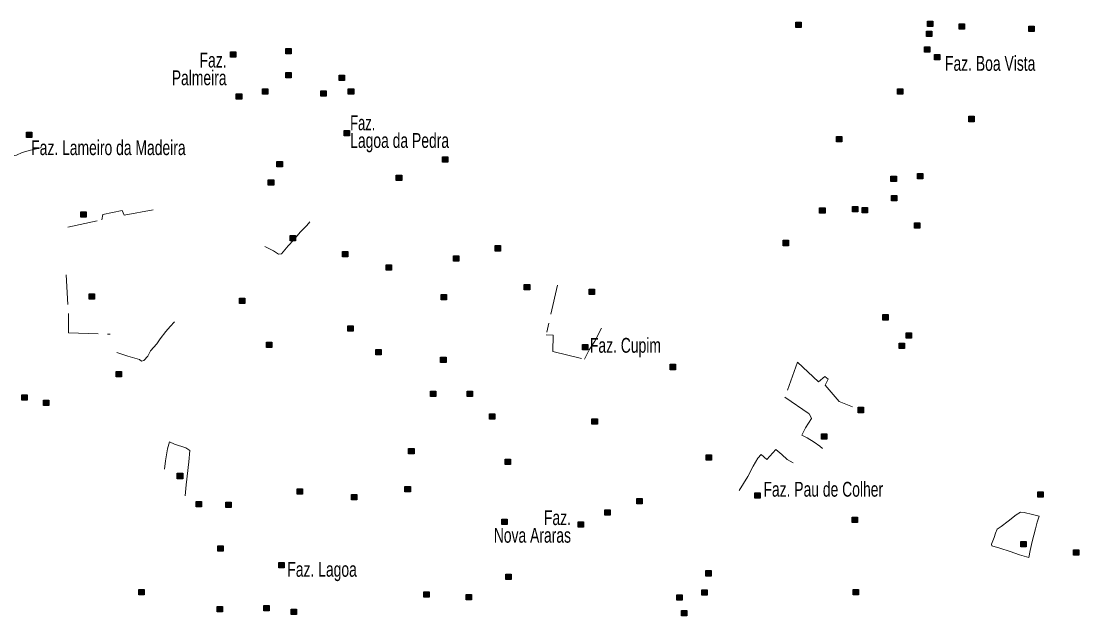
# Model space of a CAD drawing. Extents: x 445.4 to 500, y 8728.7 to 8784.
# Drawn here: x 488.04 to 499.45, y 8757.93 to 8764.34 of the extents above; entities that cross this region are included whole.
import ezdxf
from ezdxf.enums import TextEntityAlignment as Align

# ---------------------------------------------------------------- set-up
doc = ezdxf.new("R2010")
doc.units = 0
doc.header["$LTSCALE"] = 0.064
doc.linetypes.add('DOT_DASHED', pattern=[7.7, 5, -1.2, 0.3, -1.2])
doc.layers.add('2', color=7, linetype='Continuous', lineweight=25)
doc.layers.add('22', color=7, linetype='DOT_DASHED', lineweight=13)
doc.layers.add('61', color=7, linetype='Continuous')

msp = doc.modelspace()

# ---------------------------------------------------------------- hatches: boundary and pattern name
at = {"layer": '2'}
for points in [[(496.3962, 8764.3261), (496.4542, 8764.3261), (496.4542, 8764.2681), (496.3962, 8764.2681)], [(497.8159, 8764.336), (497.8739, 8764.336), (497.8739, 8764.278), (497.8159, 8764.278)], [(498.156, 8764.3064), (498.214, 8764.3064), (498.214, 8764.2484), (498.156, 8764.2484)], [(497.806, 8764.2275), (497.864, 8764.2275), (497.864, 8764.1695), (497.806, 8764.1695)], [(498.9079, 8764.2812), (498.9659, 8764.2812), (498.9659, 8764.2232), (498.9079, 8764.2232)], [(497.7814, 8764.0598), (497.8394, 8764.0598), (497.8394, 8764.0018), (497.7814, 8764.0018)], [(490.2987, 8764.0055), (490.3567, 8764.0055), (490.3567, 8763.9475), (490.2987, 8763.9475)], [(490.8959, 8764.0407), (490.9539, 8764.0407), (490.9539, 8763.9827), (490.8959, 8763.9827)], [(497.8898, 8763.976), (497.9478, 8763.976), (497.9478, 8763.918), (497.8898, 8763.918)], [(490.8952, 8763.7836), (490.9532, 8763.7836), (490.9532, 8763.7256), (490.8952, 8763.7256)], [(491.4719, 8763.754), (491.5299, 8763.754), (491.5299, 8763.696), (491.4719, 8763.696)], [(490.6438, 8763.606), (490.7018, 8763.606), (490.7018, 8763.548), (490.6438, 8763.548)], [(491.5705, 8763.606), (491.6285, 8763.606), (491.6285, 8763.548), (491.5705, 8763.548)], [(497.4905, 8763.6061), (497.5485, 8763.6061), (497.5485, 8763.5481), (497.4905, 8763.5481)], [(490.3628, 8763.5518), (490.4208, 8763.5518), (490.4208, 8763.4938), (490.3628, 8763.4938)], [(491.2747, 8763.5863), (491.3327, 8763.5863), (491.3327, 8763.5283), (491.2747, 8763.5283)], [(498.2595, 8763.3102), (498.3175, 8763.3102), (498.3175, 8763.2522), (498.2595, 8763.2522)], [(491.5261, 8763.1573), (491.5841, 8763.1573), (491.5841, 8763.0993), (491.5261, 8763.0993)], [(488.1002, 8763.1397), (488.1582, 8763.1397), (488.1582, 8763.0817), (488.1002, 8763.0817)], [(496.8349, 8763.0932), (496.8929, 8763.0932), (496.8929, 8763.0352), (496.8349, 8763.0352)], [(490.8015, 8762.8239), (490.8595, 8762.8239), (490.8595, 8762.7659), (490.8015, 8762.7659)], [(492.5859, 8762.8732), (492.6439, 8762.8732), (492.6439, 8762.8152), (492.5859, 8762.8152)], [(497.7074, 8762.6937), (497.7654, 8762.6937), (497.7654, 8762.6357), (497.7074, 8762.6357)], [(490.7078, 8762.6266), (490.7658, 8762.6266), (490.7658, 8762.5686), (490.7078, 8762.5686)], [(492.088, 8762.676), (492.146, 8762.676), (492.146, 8762.618), (492.088, 8762.618)], [(497.4215, 8762.6641), (497.4795, 8762.6641), (497.4795, 8762.6061), (497.4215, 8762.6061)], [(497.4284, 8762.4559), (497.4864, 8762.4559), (497.4864, 8762.3979), (497.4284, 8762.3979)], [(488.6868, 8762.2816), (488.7448, 8762.2816), (488.7448, 8762.2236), (488.6868, 8762.2236)], [(496.6526, 8762.3238), (496.7106, 8762.3238), (496.7106, 8762.2658), (496.6526, 8762.2658)], [(497.0075, 8762.3386), (497.0655, 8762.3386), (497.0655, 8762.2806), (497.0075, 8762.2806)], [(497.111, 8762.3288), (497.169, 8762.3288), (497.169, 8762.2708), (497.111, 8762.2708)], [(497.6745, 8762.1617), (497.7325, 8762.1617), (497.7325, 8762.1037), (497.6745, 8762.1037)], [(490.9444, 8762.025), (491.0024, 8762.025), (491.0024, 8761.967), (490.9444, 8761.967)], [(493.1527, 8761.9165), (493.2107, 8761.9165), (493.2107, 8761.8585), (493.1527, 8761.8585)], [(496.2582, 8761.9737), (496.3162, 8761.9737), (496.3162, 8761.9157), (496.2582, 8761.9157)], [(491.5064, 8761.8524), (491.5644, 8761.8524), (491.5644, 8761.7944), (491.5064, 8761.7944)], [(492.7042, 8761.808), (492.7622, 8761.808), (492.7622, 8761.75), (492.7042, 8761.75)], [(491.9796, 8761.7093), (492.0376, 8761.7093), (492.0376, 8761.6513), (491.9796, 8761.6513)], [(493.4682, 8761.4973), (493.5262, 8761.4973), (493.5262, 8761.4393), (493.4682, 8761.4393)], [(494.1682, 8761.448), (494.2262, 8761.448), (494.2262, 8761.39), (494.1682, 8761.39)], [(488.7756, 8761.3969), (488.8336, 8761.3969), (488.8336, 8761.3389), (488.7756, 8761.3389)], [(490.3973, 8761.3493), (490.4553, 8761.3493), (490.4553, 8761.2913), (490.3973, 8761.2913)], [(492.5711, 8761.3888), (492.6291, 8761.3888), (492.6291, 8761.3308), (492.5711, 8761.3308)], [(497.3328, 8761.1725), (497.3908, 8761.1725), (497.3908, 8761.1145), (497.3328, 8761.1145)], [(491.5655, 8761.0534), (491.6235, 8761.0534), (491.6235, 8760.9954), (491.5655, 8760.9954)], [(497.5842, 8760.9775), (497.6422, 8760.9775), (497.6422, 8760.9195), (497.5842, 8760.9195)], [(490.6881, 8760.8759), (490.7461, 8760.8759), (490.7461, 8760.8179), (490.6881, 8760.8179)], [(497.5103, 8760.8641), (497.5683, 8760.8641), (497.5683, 8760.8061), (497.5103, 8760.8061)], [(491.8662, 8760.797), (491.9242, 8760.797), (491.9242, 8760.739), (491.8662, 8760.739)], [(494.0942, 8760.8512), (494.1522, 8760.8512), (494.1522, 8760.7932), (494.0942, 8760.7932)], [(492.5662, 8760.7131), (492.6242, 8760.7131), (492.6242, 8760.6551), (492.5662, 8760.6551)], [(495.0407, 8760.6372), (495.0987, 8760.6372), (495.0987, 8760.5792), (495.0407, 8760.5792)], [(489.0664, 8760.5605), (489.1244, 8760.5605), (489.1244, 8760.5025), (489.0664, 8760.5025)], [(488.051, 8760.309), (488.109, 8760.309), (488.109, 8760.251), (488.051, 8760.251)], [(492.4577, 8760.3482), (492.5157, 8760.3482), (492.5157, 8760.2902), (492.4577, 8760.2902)], [(492.8521, 8760.3482), (492.9101, 8760.3482), (492.9101, 8760.2902), (492.8521, 8760.2902)], [(488.2826, 8760.2498), (488.3406, 8760.2498), (488.3406, 8760.1918), (488.2826, 8760.1918)], [(493.0936, 8760.1036), (493.1516, 8760.1036), (493.1516, 8760.0456), (493.0936, 8760.0456)], [(497.0666, 8760.1737), (497.1246, 8760.1737), (497.1246, 8760.1157), (497.0666, 8760.1157)], [(494.1977, 8760.0494), (494.2557, 8760.0494), (494.2557, 8759.9914), (494.1977, 8759.9914)], [(496.6723, 8759.8876), (496.7303, 8759.8876), (496.7303, 8759.8296), (496.6723, 8759.8296)], [(492.2211, 8759.7288), (492.2791, 8759.7288), (492.2791, 8759.6708), (492.2211, 8759.6708)], [(493.2612, 8759.6154), (493.3192, 8759.6154), (493.3192, 8759.5574), (493.2612, 8759.5574)], [(495.4301, 8759.6607), (495.4881, 8759.6607), (495.4881, 8759.6027), (495.4301, 8759.6027)], [(489.7269, 8759.4625), (489.7849, 8759.4625), (489.7849, 8759.4045), (489.7269, 8759.4045)], [(491.0184, 8759.2948), (491.0764, 8759.2948), (491.0764, 8759.2368), (491.0184, 8759.2368)], [(492.1817, 8759.3195), (492.2397, 8759.3195), (492.2397, 8759.2615), (492.1817, 8759.2615)], [(499.0064, 8759.2639), (499.0644, 8759.2639), (499.0644, 8759.2059), (499.0064, 8759.2059)], [(489.9305, 8759.1599), (489.9885, 8759.1599), (489.9885, 8759.1019), (489.9305, 8759.1019)], [(490.2494, 8759.1518), (490.3074, 8759.1518), (490.3074, 8759.0938), (490.2494, 8759.0938)], [(491.605, 8759.2356), (491.663, 8759.2356), (491.663, 8759.1776), (491.605, 8759.1776)], [(494.6809, 8759.1922), (494.7389, 8759.1922), (494.7389, 8759.1342), (494.6809, 8759.1342)], [(495.9526, 8759.2514), (496.0106, 8759.2514), (496.0106, 8759.1934), (495.9526, 8759.1934)], [(494.3358, 8759.0689), (494.3938, 8759.0689), (494.3938, 8759.0109), (494.3358, 8759.0109)], [(493.2244, 8758.9673), (493.2824, 8758.9673), (493.2824, 8758.9093), (493.2244, 8758.9093)], [(494.0495, 8758.9401), (494.1075, 8758.9401), (494.1075, 8758.8821), (494.0495, 8758.8821)], [(497.0025, 8758.99), (497.0605, 8758.99), (497.0605, 8758.932), (497.0025, 8758.932)], [(498.8204, 8758.7288), (498.8784, 8758.7288), (498.8784, 8758.6708), (498.8204, 8758.6708)], [(490.163, 8758.6801), (490.221, 8758.6801), (490.221, 8758.6221), (490.163, 8758.6221)], [(499.3894, 8758.6376), (499.4474, 8758.6376), (499.4474, 8758.5796), (499.3894, 8758.5796)], [(490.8212, 8758.5008), (490.8792, 8758.5008), (490.8792, 8758.4428), (490.8212, 8758.4428)], [(493.2676, 8758.3748), (493.3256, 8758.3748), (493.3256, 8758.3168), (493.2676, 8758.3168)], [(495.4252, 8758.413), (495.4832, 8758.413), (495.4832, 8758.355), (495.4252, 8758.355)], [(489.3128, 8758.21), (489.3708, 8758.21), (489.3708, 8758.152), (489.3128, 8758.152)], [(492.3861, 8758.1842), (492.4441, 8758.1842), (492.4441, 8758.1262), (492.3861, 8758.1262)], [(492.8422, 8758.1556), (492.9002, 8758.1556), (492.9002, 8758.0976), (492.8422, 8758.0976)], [(495.1131, 8758.1538), (495.1711, 8758.1538), (495.1711, 8758.0958), (495.1131, 8758.0958)], [(495.3808, 8758.2059), (495.4388, 8758.2059), (495.4388, 8758.1479), (495.3808, 8758.1479)], [(497.0124, 8758.2108), (497.0704, 8758.2108), (497.0704, 8758.1528), (497.0124, 8758.1528)], [(490.1558, 8758.0274), (490.2138, 8758.0274), (490.2138, 8757.9694), (490.1558, 8757.9694)], [(490.6585, 8758.0372), (490.7165, 8758.0372), (490.7165, 8757.9792), (490.6585, 8757.9792)], [(490.9543, 8757.9978), (491.0123, 8757.9978), (491.0123, 8757.9398), (490.9543, 8757.9398)], [(495.1639, 8757.9839), (495.2219, 8757.9839), (495.2219, 8757.9259), (495.1639, 8757.9259)]]:
    msp.add_hatch(color=256, dxfattribs=at).paths.add_polyline_path(points)

# ---------------------------------------------------------------- linework, layer by layer
for points in [[(496.3962, 8764.3261), (496.4542, 8764.3261), (496.4542, 8764.2681), (496.3962, 8764.2681)], [(497.8159, 8764.336), (497.8739, 8764.336), (497.8739, 8764.278), (497.8159, 8764.278)], [(498.156, 8764.3064), (498.214, 8764.3064), (498.214, 8764.2484), (498.156, 8764.2484)], [(497.806, 8764.2275), (497.864, 8764.2275), (497.864, 8764.1695), (497.806, 8764.1695)], [(498.9079, 8764.2812), (498.9659, 8764.2812), (498.9659, 8764.2232), (498.9079, 8764.2232)], [(497.7814, 8764.0598), (497.8394, 8764.0598), (497.8394, 8764.0018), (497.7814, 8764.0018)], [(490.2987, 8764.0055), (490.3567, 8764.0055), (490.3567, 8763.9475), (490.2987, 8763.9475)], [(490.8959, 8764.0407), (490.9539, 8764.0407), (490.9539, 8763.9827), (490.8959, 8763.9827)], [(497.8898, 8763.976), (497.9478, 8763.976), (497.9478, 8763.918), (497.8898, 8763.918)], [(490.8952, 8763.7836), (490.9532, 8763.7836), (490.9532, 8763.7256), (490.8952, 8763.7256)], [(491.4719, 8763.754), (491.5299, 8763.754), (491.5299, 8763.696), (491.4719, 8763.696)], [(490.6438, 8763.606), (490.7018, 8763.606), (490.7018, 8763.548), (490.6438, 8763.548)], [(491.5705, 8763.606), (491.6285, 8763.606), (491.6285, 8763.548), (491.5705, 8763.548)], [(497.4905, 8763.6061), (497.5485, 8763.6061), (497.5485, 8763.5481), (497.4905, 8763.5481)], [(490.3628, 8763.5518), (490.4208, 8763.5518), (490.4208, 8763.4938), (490.3628, 8763.4938)], [(491.2747, 8763.5863), (491.3327, 8763.5863), (491.3327, 8763.5283), (491.2747, 8763.5283)], [(498.2595, 8763.3102), (498.3175, 8763.3102), (498.3175, 8763.2522), (498.2595, 8763.2522)], [(491.5261, 8763.1573), (491.5841, 8763.1573), (491.5841, 8763.0993), (491.5261, 8763.0993)], [(488.1002, 8763.1397), (488.1582, 8763.1397), (488.1582, 8763.0817), (488.1002, 8763.0817)], [(496.8349, 8763.0932), (496.8929, 8763.0932), (496.8929, 8763.0352), (496.8349, 8763.0352)], [(490.8015, 8762.8239), (490.8595, 8762.8239), (490.8595, 8762.7659), (490.8015, 8762.7659)], [(492.5859, 8762.8732), (492.6439, 8762.8732), (492.6439, 8762.8152), (492.5859, 8762.8152)], [(497.7074, 8762.6937), (497.7654, 8762.6937), (497.7654, 8762.6357), (497.7074, 8762.6357)], [(490.7078, 8762.6266), (490.7658, 8762.6266), (490.7658, 8762.5686), (490.7078, 8762.5686)], [(492.088, 8762.676), (492.146, 8762.676), (492.146, 8762.618), (492.088, 8762.618)], [(497.4215, 8762.6641), (497.4795, 8762.6641), (497.4795, 8762.6061), (497.4215, 8762.6061)], [(497.4284, 8762.4559), (497.4864, 8762.4559), (497.4864, 8762.3979), (497.4284, 8762.3979)], [(488.6868, 8762.2816), (488.7448, 8762.2816), (488.7448, 8762.2236), (488.6868, 8762.2236)], [(496.6526, 8762.3238), (496.7106, 8762.3238), (496.7106, 8762.2658), (496.6526, 8762.2658)], [(497.0075, 8762.3386), (497.0655, 8762.3386), (497.0655, 8762.2806), (497.0075, 8762.2806)], [(497.111, 8762.3288), (497.169, 8762.3288), (497.169, 8762.2708), (497.111, 8762.2708)], [(497.6745, 8762.1617), (497.7325, 8762.1617), (497.7325, 8762.1037), (497.6745, 8762.1037)], [(490.9444, 8762.025), (491.0024, 8762.025), (491.0024, 8761.967), (490.9444, 8761.967)], [(493.1527, 8761.9165), (493.2107, 8761.9165), (493.2107, 8761.8585), (493.1527, 8761.8585)], [(496.2582, 8761.9737), (496.3162, 8761.9737), (496.3162, 8761.9157), (496.2582, 8761.9157)], [(491.5064, 8761.8524), (491.5644, 8761.8524), (491.5644, 8761.7944), (491.5064, 8761.7944)], [(492.7042, 8761.808), (492.7622, 8761.808), (492.7622, 8761.75), (492.7042, 8761.75)], [(491.9796, 8761.7093), (492.0376, 8761.7093), (492.0376, 8761.6513), (491.9796, 8761.6513)], [(493.4682, 8761.4973), (493.5262, 8761.4973), (493.5262, 8761.4393), (493.4682, 8761.4393)], [(494.1682, 8761.448), (494.2262, 8761.448), (494.2262, 8761.39), (494.1682, 8761.39)], [(488.7756, 8761.3969), (488.8336, 8761.3969), (488.8336, 8761.3389), (488.7756, 8761.3389)], [(490.3973, 8761.3493), (490.4553, 8761.3493), (490.4553, 8761.2913), (490.3973, 8761.2913)], [(492.5711, 8761.3888), (492.6291, 8761.3888), (492.6291, 8761.3308), (492.5711, 8761.3308)], [(497.3328, 8761.1725), (497.3908, 8761.1725), (497.3908, 8761.1145), (497.3328, 8761.1145)], [(491.5655, 8761.0534), (491.6235, 8761.0534), (491.6235, 8760.9954), (491.5655, 8760.9954)], [(497.5842, 8760.9775), (497.6422, 8760.9775), (497.6422, 8760.9195), (497.5842, 8760.9195)], [(490.6881, 8760.8759), (490.7461, 8760.8759), (490.7461, 8760.8179), (490.6881, 8760.8179)], [(497.5103, 8760.8641), (497.5683, 8760.8641), (497.5683, 8760.8061), (497.5103, 8760.8061)], [(491.8662, 8760.797), (491.9242, 8760.797), (491.9242, 8760.739), (491.8662, 8760.739)], [(494.0942, 8760.8512), (494.1522, 8760.8512), (494.1522, 8760.7932), (494.0942, 8760.7932)], [(492.5662, 8760.7131), (492.6242, 8760.7131), (492.6242, 8760.6551), (492.5662, 8760.6551)], [(495.0407, 8760.6372), (495.0987, 8760.6372), (495.0987, 8760.5792), (495.0407, 8760.5792)], [(489.0664, 8760.5605), (489.1244, 8760.5605), (489.1244, 8760.5025), (489.0664, 8760.5025)], [(488.051, 8760.309), (488.109, 8760.309), (488.109, 8760.251), (488.051, 8760.251)], [(492.4577, 8760.3482), (492.5157, 8760.3482), (492.5157, 8760.2902), (492.4577, 8760.2902)], [(492.8521, 8760.3482), (492.9101, 8760.3482), (492.9101, 8760.2902), (492.8521, 8760.2902)], [(488.2826, 8760.2498), (488.3406, 8760.2498), (488.3406, 8760.1918), (488.2826, 8760.1918)], [(493.0936, 8760.1036), (493.1516, 8760.1036), (493.1516, 8760.0456), (493.0936, 8760.0456)], [(497.0666, 8760.1737), (497.1246, 8760.1737), (497.1246, 8760.1157), (497.0666, 8760.1157)], [(494.1977, 8760.0494), (494.2557, 8760.0494), (494.2557, 8759.9914), (494.1977, 8759.9914)], [(496.6723, 8759.8876), (496.7303, 8759.8876), (496.7303, 8759.8296), (496.6723, 8759.8296)], [(492.2211, 8759.7288), (492.2791, 8759.7288), (492.2791, 8759.6708), (492.2211, 8759.6708)], [(493.2612, 8759.6154), (493.3192, 8759.6154), (493.3192, 8759.5574), (493.2612, 8759.5574)], [(495.4301, 8759.6607), (495.4881, 8759.6607), (495.4881, 8759.6027), (495.4301, 8759.6027)], [(489.7269, 8759.4625), (489.7849, 8759.4625), (489.7849, 8759.4045), (489.7269, 8759.4045)], [(491.0184, 8759.2948), (491.0764, 8759.2948), (491.0764, 8759.2368), (491.0184, 8759.2368)], [(492.1817, 8759.3195), (492.2397, 8759.3195), (492.2397, 8759.2615), (492.1817, 8759.2615)], [(499.0064, 8759.2639), (499.0644, 8759.2639), (499.0644, 8759.2059), (499.0064, 8759.2059)], [(489.9305, 8759.1599), (489.9885, 8759.1599), (489.9885, 8759.1019), (489.9305, 8759.1019)], [(490.2494, 8759.1518), (490.3074, 8759.1518), (490.3074, 8759.0938), (490.2494, 8759.0938)], [(491.605, 8759.2356), (491.663, 8759.2356), (491.663, 8759.1776), (491.605, 8759.1776)], [(494.6809, 8759.1922), (494.7389, 8759.1922), (494.7389, 8759.1342), (494.6809, 8759.1342)], [(495.9526, 8759.2514), (496.0106, 8759.2514), (496.0106, 8759.1934), (495.9526, 8759.1934)], [(494.3358, 8759.0689), (494.3938, 8759.0689), (494.3938, 8759.0109), (494.3358, 8759.0109)], [(493.2244, 8758.9673), (493.2824, 8758.9673), (493.2824, 8758.9093), (493.2244, 8758.9093)], [(494.0495, 8758.9401), (494.1075, 8758.9401), (494.1075, 8758.8821), (494.0495, 8758.8821)], [(497.0025, 8758.99), (497.0605, 8758.99), (497.0605, 8758.932), (497.0025, 8758.932)], [(498.8204, 8758.7288), (498.8784, 8758.7288), (498.8784, 8758.6708), (498.8204, 8758.6708)], [(490.163, 8758.6801), (490.221, 8758.6801), (490.221, 8758.6221), (490.163, 8758.6221)], [(499.3894, 8758.6376), (499.4474, 8758.6376), (499.4474, 8758.5796), (499.3894, 8758.5796)], [(490.8212, 8758.5008), (490.8792, 8758.5008), (490.8792, 8758.4428), (490.8212, 8758.4428)], [(493.2676, 8758.3748), (493.3256, 8758.3748), (493.3256, 8758.3168), (493.2676, 8758.3168)], [(495.4252, 8758.413), (495.4832, 8758.413), (495.4832, 8758.355), (495.4252, 8758.355)], [(489.3128, 8758.21), (489.3708, 8758.21), (489.3708, 8758.152), (489.3128, 8758.152)], [(492.3861, 8758.1842), (492.4441, 8758.1842), (492.4441, 8758.1262), (492.3861, 8758.1262)], [(492.8422, 8758.1556), (492.9002, 8758.1556), (492.9002, 8758.0976), (492.8422, 8758.0976)], [(495.1131, 8758.1538), (495.1711, 8758.1538), (495.1711, 8758.0958), (495.1131, 8758.0958)], [(495.3808, 8758.2059), (495.4388, 8758.2059), (495.4388, 8758.1479), (495.3808, 8758.1479)], [(497.0124, 8758.2108), (497.0704, 8758.2108), (497.0704, 8758.1528), (497.0124, 8758.1528)], [(490.1558, 8758.0274), (490.2138, 8758.0274), (490.2138, 8757.9694), (490.1558, 8757.9694)], [(490.6585, 8758.0372), (490.7165, 8758.0372), (490.7165, 8757.9792), (490.6585, 8757.9792)], [(490.9543, 8757.9978), (491.0123, 8757.9978), (491.0123, 8757.9398), (490.9543, 8757.9398)], [(495.1639, 8757.9839), (495.2219, 8757.9839), (495.2219, 8757.9259), (495.1639, 8757.9259)]]:
    msp.add_lwpolyline(points, close=True, dxfattribs=at)
at = {"layer": '22'}
for points in [[(487.7033, 8762.8333), (487.7745, 8762.8446), (487.9034, 8762.8721), (487.9928, 8762.8928), (488.0546, 8762.9185), (488.1423, 8762.9443), (488.2282, 8762.965), (488.2572, 8762.9759)], [(488.5481, 8762.116), (488.9139, 8762.1947), (488.9224, 8762.2534), (489.1305, 8762.2959), (489.1533, 8762.2457), (489.5441, 8762.317)], [(490.6706, 8761.907), (490.7622, 8761.8587), (490.8167, 8761.8241), (490.8496, 8761.8291), (490.9205, 8761.9148), (490.9815, 8761.9792), (491.0524, 8762.06), (491.1217, 8762.1342), (491.1563, 8762.1739)], [(488.5272, 8761.6026), (488.5526, 8761.1763), (488.5526, 8760.9771), (489.0033, 8760.9609)], [(493.8272, 8761.4895), (493.7042, 8760.9531), (493.7788, 8760.9496), (493.7752, 8760.7757), (494.1164, 8760.694), (494.1661, 8760.7934), (494.2301, 8760.8857), (494.3002, 8761.0262)], [(489.0764, 8760.7633), (489.194, 8760.7251), (489.318, 8760.6875), (489.3405, 8760.6724), (489.3668, 8760.68), (489.4081, 8760.7251), (489.4382, 8760.7815), (489.5058, 8760.8567), (489.5434, 8760.9131), (489.6035, 8760.992), (489.6486, 8761.0446), (489.6966, 8761.0965)], [(497.008, 8760.1792), (496.8626, 8760.2356), (496.7104, 8760.4121), (496.7432, 8760.4787), (496.7095, 8760.5054), (496.64, 8760.4487), (496.4121, 8760.6608), (496.2772, 8760.284), (496.5428, 8760.1), (496.563, 8760.0525), (496.5014, 8759.9512)], [(496.5014, 8759.9512), (496.4612, 8759.8747), (496.5176, 8759.8446), (496.5927, 8759.7995), (496.6534, 8759.7554), (496.6823, 8759.7312)], [(489.8104, 8759.22), (489.8222, 8759.3368), (489.8523, 8759.585), (489.8635, 8759.709), (489.8184, 8759.7353), (489.6982, 8759.7767), (489.6418, 8759.803), (489.6204, 8759.727), (489.6155, 8759.6827), (489.6005, 8759.5962), (489.5895, 8759.5079)], [(495.7833, 8759.2762), (495.8781, 8759.4275), (495.937, 8759.5379), (495.9856, 8759.6252), (496.0214, 8759.6637), (496.0829, 8759.6098), (496.1802, 8759.7202), (496.2442, 8759.6663), (496.303, 8759.6124), (496.3671, 8759.5736)]]:
    msp.add_lwpolyline(points, dxfattribs=at)
msp.add_lwpolyline([(498.507, 8758.6967), (498.5133, 8758.7171), (498.5337, 8758.7694), (498.5502, 8758.8179), (498.568, 8758.8613), (498.61, 8758.8881), (498.686, 8758.9456), (498.7729, 8759.0131), (498.8179, 8759.0448), (498.8568, 8759.0412), (498.9471, 8759.0195), (499.0184, 8759.0016), (498.9993, 8758.9353), (498.979, 8758.8625), (498.9446, 8758.7273), (498.9242, 8758.6303), (498.9064, 8758.5537), (498.8085, 8758.5844), (498.708, 8758.6188), (498.5947, 8758.6571), (498.5082, 8758.6814)], close=True, dxfattribs=at)

# ---------------------------------------------------------------- texts
at = {"layer": '61', "width": 0.7}
for s, p in [('         Faz.', (490.2579, 8763.836)), ('Palmeira', (490.2579, 8763.646)), ('Faz. Cupim', (494.9412, 8760.7618)), ('             Faz.', (493.9714, 8758.9043)), ('Nova Araras', (493.9714, 8758.7143))]:
    msp.add_text(s, height=0.16, dxfattribs=at).set_placement(p, align=Align.RIGHT)
at = {"layer": '61'}
for s, width, p in [('Faz. Boa Vista', 0.7, (498.0045, 8763.8011)), ('Faz.', 0.65, (491.591, 8763.1599)), ('Faz. Lameiro da Madeira', 0.7, (488.1514, 8762.8924)), ('Lagoa da Pedra', 0.7, (491.591, 8762.9699)), ('Faz. Pau de Colher', 0.7, (496.0463, 8759.2103)), ('Faz. Lagoa', 0.7, (490.9131, 8758.3474))]:
    msp.add_text(s, height=0.16, dxfattribs=dict(at, width=width)).set_placement(p)

doc.saveas('drawing.dxf')
